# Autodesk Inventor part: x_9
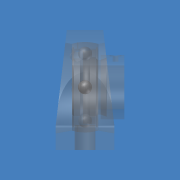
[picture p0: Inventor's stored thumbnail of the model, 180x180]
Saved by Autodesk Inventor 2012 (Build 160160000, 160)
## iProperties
Company: CAD-Verlag
Part Number: x_9
Document SubType Name: Modeling
Created: 2004-09
Material: Standard
Designer: Greiling
Manufacturer: Standard
Standards Organization: Custom
Density: 1 g/cm^3
Control State: 0
Master: False
Checked Out: False
Shininess: 64.0
Length Units: 11269
Angle Units: 11279
Time Units: 11290
Mass Units: 11283
Length Display Precision: 3
Angle Display Precision: 2
Compacted: True
Übersetzungsnorm: STEP AP214CD
Dateiname: w2c22665.stp
Vorprozessor: ACIS
Postprozessor: Build: 081d, Release: 8 SP1 - Date: Tue 01/26/2004
Gesendete Einheiten: MILLIMETERS
Unbestimmtheit: 1e-06
Density: 0.0
Volumn: 0.0
Area: 0.0
PropertySet Name: Model Information
Author: Jürgen Kronas
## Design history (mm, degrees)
feature "Basis1"
node "Volumenkörper1"
node "Volumenkörpern"
node "Oberflächenkörpern"
